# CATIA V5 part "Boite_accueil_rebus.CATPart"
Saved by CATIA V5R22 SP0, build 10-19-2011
Part number: Boite_accueil_rebus
Bounding box of the stored display mesh (mm): x 0 to 20, y 0 to 230, z 0 to 126
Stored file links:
  C:\Users\La forge\Desktop\CAO_PER_pick&place_2023A\Sous_Ensemble_Boite\Reservoir_Boite\Boite_accueil_rebus.CATPart
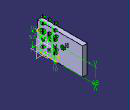
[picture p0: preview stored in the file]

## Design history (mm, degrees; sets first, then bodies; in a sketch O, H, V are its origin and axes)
Body1 (main body)
  Sketch1 on yz-plane, origin (0, 0, 0), H (0, 1, 0), V (0, 0, 1)
    line L1 (0, 0) -> (200, 0)
    line L2 (200, 0) -> (200, 120)
    line L3 (200, 120) -> (0, 120)
    line L4 (0, 120) -> (0, 0)
    point P1 (200, 0)
    point P2 (200, 120)
    distance P1 O = 200
    distance P2 P1 = 120
    horizontal: L1 H, L3 H
    vertical: L2 V, L4 V
  Pad1: profile Sketch1, direction (1, 0, 0), length 20
  Sketch2 on end face of Pad1, origin (20, 0, 0), H (0, 1, 0), V (0, 0, 1)
    point P1 (10, 10)
    line L1 (10, 10) -> (63, 10)
    line L2 (63, 10) -> (63, 63)
    line L3 (63, 63) -> (10, 63)
    line L4 (10, 63) -> (10, 10)
    point P2 (63, 10)
    point P3 (63, 63)
    point P4 (10, 63)
    reference projected line E1 (0, 0) -> (200, 0) from edge [face of Pad1 from Sketch1.L1 | end face of Pad1]
    reference projected line E2 (0, 120) -> (0, 0) from edge [face of Pad1 from Sketch1.L4 | end face of Pad1]
    axis line L5 (0, 68) -> (230, 68)
    point P5 (0, 68)
    reference projected line E3 (0, 0) -> (200, 0) from edge [face of Pad1 from Sketch1.L1 | end face of Pad1]
    point P7 (10, 73)
    point P8 (63, 73)
    line L6 (63, 73) -> (10, 73)
    point P9 (63, 126)
    line L7 (63, 126) -> (63, 73)
    point P10 (10, 126)
    line L8 (10, 126) -> (63, 126)
    line L9 (10, 73) -> (10, 126)
    distance P1 E1 = 10
    distance P1 E2 = 10
    distance P4 P3 = 53
    distance P3 P2 = 53
    distance L5 E3 = 68
    horizontal: L1 H, L3 H, L5 H
    vertical: L2 V, L4 V
    coincidence: P5 V
    symmetry: P4 P7 L5, P3 P8 L5, L3 L6 L5, P2 P9 L5, L2 L7 L5, P1 P10 L5, L1 L8 L5, L4 L9 L5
